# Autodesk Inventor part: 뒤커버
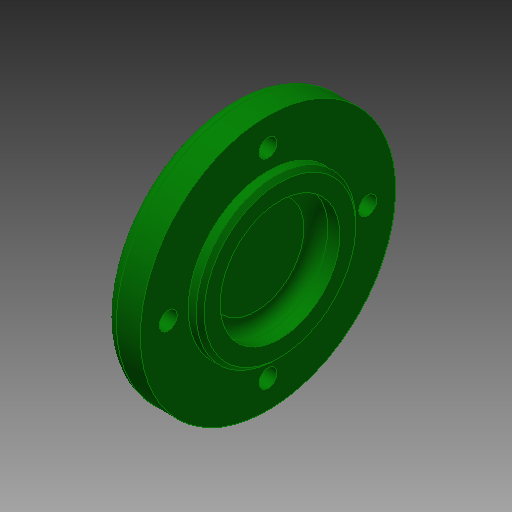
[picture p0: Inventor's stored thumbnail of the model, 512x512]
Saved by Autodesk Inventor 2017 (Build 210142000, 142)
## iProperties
Created: 2020-07
Part Number: 뒤커버
Material: 알루미늄 6061
Document SubType Name: Modeling
Designer: mduedu
Density: 2.71 g/cm^3
Appearance: 진녹색
Mass: 73.2683 g
Surface Area: 92.9808 cm^2
Volume: 27.0363 cm^3
Author: mduedu
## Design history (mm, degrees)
sketch "스케치1"
  geometry: L1 (0, 0)-(9, 0); L2 (9, 0)-(9, 32); L3 (9, 32)-(0, 32); L4 (0, 32)-(0, 0); L5 (9, 0)-(12, 0); L6 (12, 0)-(12, 20); L7 (12, 20)-(9, 20); L8 (9, 20)-(9, 0)
  constraints: 16 end point, 4 parallel, 2 horizontal, 2 perpendicular
  dimensions: "d0" = 64 diameter of L3 L1; "d2" = 40 diameter of L7 L5; "d3" = 3 distance of L6.end L7.end; "d4" = 12 distance between parallel lines of L4 L6
revolve "회전1" sketch "스케치1" stored, may be unused: angle "d5" = 90 deg
sketch "스케치2"
  geometry: C1 r 15 at (0, 0); 1 further point
  constraints: 1 centre point, 1 coincident
  dimensions: "d6" = 30 diameter of C1
extrude "돌출1" cut sketch "스케치2" distance "d7" = 6; taper "d8" = 0 deg
fillet "모깎기1" dims "d9" = 3
fillet "모깎기2" dims "d10" = 3
chamfer "모따기1" distance "d11" = 1; stored, may be unused: second distance "d12" = 2, angle "d13" = 45 deg
sketch "스케치3" dims "d14" = 50
  geometry: 3 further points
  constraints: 2 vertical alignment, 1 coincident, 2 other
hole "구멍1" sketch "스케치3" at (0, 25) diameter "d15" = 4.5; stored, may be unused: countersink angle "d19" = 90 deg, drill point angle "d21" = 118 deg; dims "d16" = 6, "d17" = 8, "d18" = 4.4, "d20" = 8
node "솔리드1"
pattern_circular "원형 패턴1" dims angle "d23" = 360 deg
